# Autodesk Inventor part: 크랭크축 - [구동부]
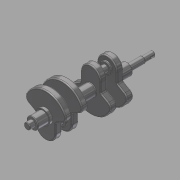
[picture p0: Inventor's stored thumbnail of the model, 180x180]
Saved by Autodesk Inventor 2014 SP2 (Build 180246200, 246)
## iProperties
Created: 2017-03
Part Number: 크랭크축 - [구동부]
Material: 강철, 탄소
Document SubType Name: Modeling
Designer: mduedu
Density: 7.87 g/cm^3
Mass: 1840.77 g
Surface Area: 500.249 cm^2
Volume: 233.897 cm^3
Appearance: 반광택
Author: mduedu
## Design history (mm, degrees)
sketch "스케치1" dims "d5" = 57
  geometry: L1 (-19, 21.243)-(-19, 3.243); L2 (-19, 3.243)-(-40.023, -8.895); L3 (19, 21.243)-(19, 3.243); L4 (0, 21.243)-(0, -41); L5 (19, 3.243)-(40.023, -8.895); C1 r 6 at (0, 0); C2 r 13.5 at (0, 0); A1 r 41 centre (0, 0) between (-40.023, -8.895) and (0, -41); A2 r 41 centre (0, 0) between (0, -41) and (40.023, -8.895); A3 r 19 centre (0, 21.243) between (19, 21.243) and (0, 40.243); A4 r 19 centre (0, 21.243) between (0, 40.243) and (-19, 21.243); 3 further points
  constraints: 10 end point, 8 point on circle, 6 centre point, 5 coincident, 3 symmetric about line, 2 point on line, 1 parallel, 1 tangent, 1 vertical, 1 vertical alignment, 5 other
  dimensions: "d0" = 12 diameter of C1; "d1" = 27 diameter of C2; "d2" = 18 distance of L1.start L1.end; "d3" = 120 deg angle of L2 L1; "d4" = 41 radius of A1; "d6" = 19 radius of A4
extrude "돌출1" new body sketch "스케치1" distance "d7" = 12; taper "d8" = 0 deg
extrude "돌출2" join sketch "스케치1" distance "d9" = 5; taper "d10" = 0 deg
extrude "돌출3" join sketch "스케치1" distance "d11" = 75; taper "d12" = 0 deg
sketch "스케치2"
  geometry: C1 r 11 at (0, 21.243); C2 r 6 at (0, 21.243); A1 r 19 centre (0, 21.243) between (19, 21.243) and (-19, 21.243) reference; 1 further point
  constraints: 2 centre point, 2 coincident
  dimensions: "d13" = 22 diameter of C1; "d14" = 12 diameter of C2
extrude "돌출4" join sketch "스케치2" distance "d15" = 3; taper "d16" = 0 deg
extrude "돌출5" join sketch "스케치2" distance "d17" = 16; taper "d18" = 0 deg
fillet "모깎기1" dims "d19" = 3, "d20" = 10
fillet "모깎기2" dims "d21" = 2
sketch "스케치3"
  geometry: C1 r 11 at (0, 0); 1 further point
  constraints: 1 centre point, 1 coincident
  dimensions: "d22" = 22 diameter of C1
extrude "돌출6" join sketch "스케치3" distance "d23" = 21; taper "d24" = 0 deg
sketch "스케치4"
  geometry: C1 r 6 at (0, 0) reference; C2 r 5 at (0, 0); 1 further point
  constraints: 1 centre point
  dimensions: "d25" = 1 radial gap between concentric circles of C1 C2
extrude "돌출7" cut sketch "스케치4" distance "d26" = 20; taper "d27" = 0 deg
node "작업 평면1"
sketch "스케치5"
  geometry: L1 (-5, 0)-(5, 0) reference; L2 (-1.5, 0)-(1.5, 0); L3 (1.5, 0)-(1.5, 8.5); L4 (-1.5, 8.5)-(-1.5, 0); A1 r 1.5 centre (0, 8.5) between (1.5, 8.5) and (-1.5, 8.5); 1 further point
  constraints: 6 end point, 2 point on circle, 2 tangent, 1 centre point, 1 horizontal, 1 parallel, 1 perpendicular, 1 point on line, 1 vertical alignment
  dimensions: "d28" = 3 distance between parallel lines of L3 L4; "d30" = 10 dimension on A1 L1
extrude "돌출8" cut sketch "스케치5" distance "d31" = 1.8; taper "d32" = 0 deg
chamfer "모따기1" distance "d33" = 1; stored, may be unused: second distance "d34" = 2, angle "d35" = 45 deg
chamfer "모따기2" distance "d36" = 1; stored, may be unused: second distance "d37" = 2, angle "d38" = 45 deg
node "작업 평면2"
sketch "스케치6"
  geometry: C1 r 11 at (0, 0) reference; C2 r 11 at (0, 0) reference; 1 further point
extrude "돌출9" join sketch "스케치6" distance "d39" = 42; taper "d40" = 0 deg
sketch "스케치7" dims "d46" = 57
  geometry: L1 (-19, -21.243)-(-19, -3.243); L2 (19, -21.243)-(19, -3.243); L3 (-19, -3.243)-(-40.023, 8.895); L4 (19, -3.243)-(40.023, 8.895); L5 (0, -21.243)-(0, 41); C1 r 13.5 at (0, 0); C2 r 6 at (0, 0); A1 r 19 centre (0, -21.243) between (0, -40.243) and (19, -21.243); A2 r 19 centre (0, -21.243) between (-19, -21.243) and (0, -40.243); A3 r 41 centre (0, 0) between (0, 41) and (-40.023, 8.895); A4 r 41 centre (0, 0) between (40.023, 8.895) and (0, 41); 3 further points
  constraints: 10 end point, 8 point on circle, 6 centre point, 5 coincident, 3 symmetric about line, 2 point on line, 1 parallel, 1 tangent, 1 vertical, 5 other
  dimensions: "d41" = 12 diameter of C2; "d42" = 27 diameter of C1; "d43" = 18 distance of L2.start L2.end; "d44" = 120 deg angle of L4 L2; "d45" = 41 radius of A4; "d47" = 19 radius of A1
extrude "돌출10" join sketch "스케치7" distance "d48" = 12; taper "d49" = 0 deg
sketch "스케치8"
  geometry: C1 r 11 at (0, -21.243); C2 r 6 at (0, -21.243); A1 r 19 centre (0, -21.243) between (-19, -21.243) and (19, -21.243) reference; 1 further point
  constraints: 2 centre point, 2 coincident
  dimensions: "d50" = 22 diameter of C1; "d51" = 12 diameter of C2
extrude "돌출11" join sketch "스케치8" distance "d52" = 3; taper "d53" = 0 deg
extrude "돌출12" join sketch "스케치8" distance "d54" = 16; taper "d55" = 0 deg
fillet "모깎기3" dims "d56" = 3, "d57" = 10
fillet "모깎기4" dims "d58" = 2
chamfer "모따기3" distance "d59" = 1; stored, may be unused: second distance "d60" = 2, angle "d61" = 45 deg
node "작업 평면3"
fillet "모깎기5" dims "d62" = 1
sketch "스케치9"
  geometry: C1 r 13.5 at (0, 0) reference; 1 further point
extrude "돌출13" join sketch "스케치9" distance "d63" = 5; taper "d64" = 0 deg
sketch "스케치10"
  geometry: C1 r 6 at (0, 0) reference; 1 further point
extrude "돌출14" join sketch "스케치10" distance "d65" = 30; taper "d66" = 0 deg
sketch "스케치11"
  geometry: C1 r 11 at (0, 0); 1 further point
  constraints: 1 centre point, 1 coincident
  dimensions: "d67" = 22 diameter of C1
extrude "돌출15" join sketch "스케치11" distance "d68" = 20; taper "d69" = 0 deg
chamfer "모따기4" distance "d70" = 1; stored, may be unused: second distance "d71" = 2, angle "d72" = 45 deg
chamfer "모따기5" distance "d75" = 0.7; stored, may be unused: second distance "d76" = 2, angle "d77" = 30 deg
fillet "모깎기6" dims "d78" = 0.3
node "솔리드1"
mirror "대칭1"
mirror "대칭2"
node "투영된 루프1"
